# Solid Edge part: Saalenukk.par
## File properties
Author: Türk
Template: Iso Part.par
Last saved by: Türk
Revision: 5
Application: Solid Edge
Accuracy: 0,990
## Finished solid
Body 1: solid body, 4 faces, 4 edges, 0 vertices.
  Faces by surface: cylinder 2, plane 2
  Edges by curve: circle 4
Bounding box of the edges (mm): 25.000 x 12.000 x 25.000, from (-12.5, 0, -12.5) to (12.5, 12, 12.5).
Cylindrical faces by radius (mm): R12 x1, R12.5 x1
Planar faces by outward normal: +y 1, -y 1
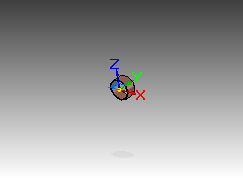
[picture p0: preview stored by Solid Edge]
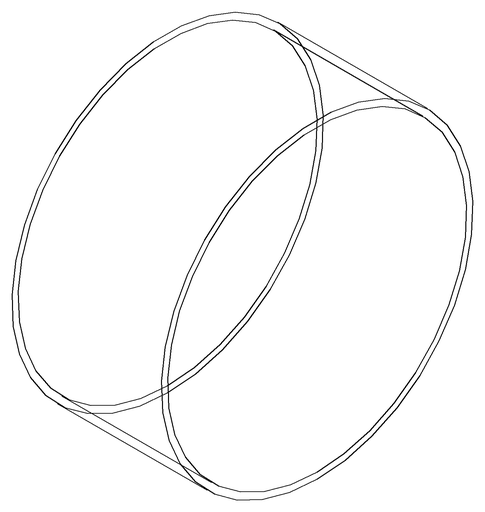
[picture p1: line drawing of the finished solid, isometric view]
